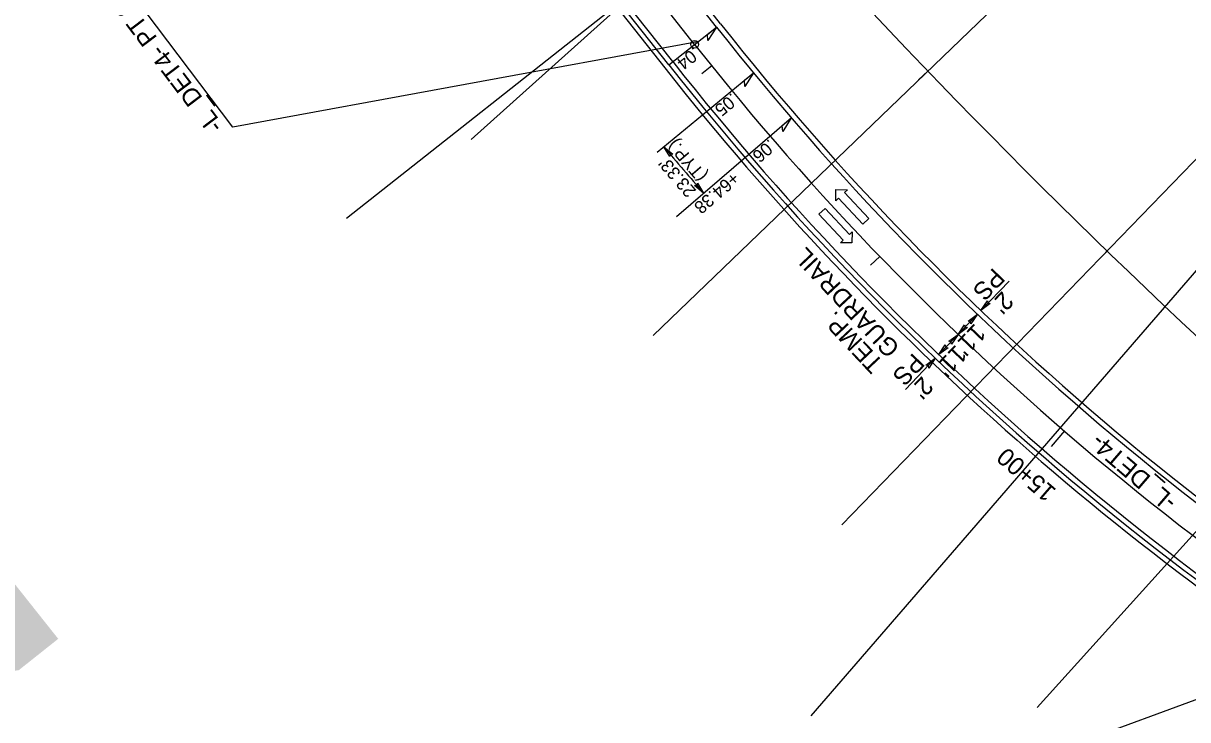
# Model space of a CAD drawing. Extents: x 473658 to 481584, y 489119 to 506230.
# Drawn here: x 476198.9 to 476657.4, y 500561 to 500835 of the extents above; entities that cross this region are included whole.
import ezdxf

# ---------------------------------------------------------------- set-up
doc = ezdxf.new("R2010")
doc.units = 0
for name, color, linetype in [('Exist Horizontal Alignment', 7, 'Continuous'), ('Prop Dimension', 7, 'Continuous'), ('Prop EOT', 7, 'Continuous'), ('Prop Guardrail', 7, 'Continuous'), ('Prop Horizontal Alignment', 7, 'Continuous'), ('Prop Horizontal Alignment Direction Label', 7, 'Continuous'), ('Prop Horizontal Alignment Station Label', 7, 'Continuous'), ('Prop Horizontal Alignment Tick Label', 7, 'Continuous'), ('Prop Horizontal Alignment Tick Large', 7, 'Continuous'), ('Prop Horizontal Alignment Tick Small', 7, 'Continuous'), ('Prop Paved Shoulder', 7, 'Continuous'), ('Prop Shade Medium', 7, 'Continuous'), ('Prop Superelevation  Arrow CELL', 7, 'Continuous'), ('Prop Superelevation Label', 7, 'Continuous'), ('Scratch_Level_6', 7, 'Continuous'), ('Sheet Block Title CELL', 7, 'Continuous'), ('Sheet Plan And Profile CELL', 7, 'Continuous'), ('Sheet Profile Grid Major CELL', 7, 'Continuous')]:
    doc.layers.add(name, color=color, linetype=linetype)

msp = doc.modelspace()

# ---------------------------------------------------------------- linework, layer by layer
at = {"layer": 'Exist Horizontal Alignment'}
for points in [[(476579.63, 500724.73), (476575.96, 500722.01), (476578.51, 500725.83), (476578.69, 500724.86)], [(476570.91, 500717.85), (476574.58, 500720.56), (476572.03, 500716.74), (476571.85, 500717.71)], [(476570.65, 500715.33), (476566.98, 500712.61), (476569.53, 500716.44), (476569.71, 500715.47)], [(476563.31, 500709.9), (476566.98, 500712.61), (476564.43, 500708.79), (476564.25, 500709.76)], [(476563.04, 500707.38), (476559.37, 500704.66), (476561.92, 500708.49), (476562.1, 500707.52)], [(476554.32, 500700.5), (476557.99, 500703.22), (476555.44, 500699.39), (476555.26, 500700.36)]]:
    msp.add_lwpolyline(points, close=True, dxfattribs=at)
at = {"layer": 'Prop Dimension'}
for p, q in [((476575.96, 500722.01), (476587.03, 500733.58)), ((476559.37, 500704.66), (476574.58, 500720.56)), ((476546.24, 500690.93), (476557.99, 500703.22))]:
    msp.add_line(p, q, dxfattribs=at)
at = {"layer": 'Prop EOT'}
for p, q in [((476471.89, 500833.57), (476404.54, 500919.03)), ((476454.61, 500819.95), (476387.26, 500905.41))]:
    msp.add_line(p, q, dxfattribs=at)
for radius, end in [(1089, 241.8577), (1111, 241.40091)]:
    msp.add_arc((477327.21, 501507.62), radius, 218.24077, end, dxfattribs=at)
at = {"layer": 'Prop Guardrail'}
msp.add_line((476384.12, 500902.94), (476451.47, 500817.48), dxfattribs=at)
msp.add_arc((477327.21, 501507.62), 1115, 218.24077, 239.00479, dxfattribs=at)
at = {"layer": 'Prop Horizontal Alignment'}
msp.add_line((476463.25, 500826.76), (476395.9, 500912.22), dxfattribs=at)
for centre, radius, start, end in [((478615.62, 502799.59), 2860, 203.81642, 228.24762), ((477327.21, 501507.62), 1100, 218.24077, 241.8577)]:
    msp.add_arc(centre, radius, start, end, dxfattribs=at)
at = {"layer": 'Prop Horizontal Alignment Station Label'}
for p, q in [((476281.48, 500794.12), (476201.88, 500899.28)), ((476464.43, 500827.69), (476281.48, 500794.12)), ((476772.09, 500609.96), (476453.22, 500492.62))]:
    msp.add_line(p, q, dxfattribs=at)
msp.add_circle((476463.25, 500826.76), 1.5, dxfattribs=at)
at = {"layer": 'Prop Horizontal Alignment Tick Large'}
msp.add_line((476608.81, 500674.62), (476603.58, 500668.56), dxfattribs=at)
at = {"layer": 'Prop Horizontal Alignment Tick Small'}
for p, q in [((476469.99, 500818.3), (476466.09, 500815.17)), ((476555.03, 500816.27), (476551.43, 500812.8)), ((476536.13, 500743.3), (476532.53, 500739.83)), ((476625.62, 500745.44), (476622.15, 500741.85))]:
    msp.add_line(p, q, dxfattribs=at)
at = {"layer": 'Prop Paved Shoulder'}
for p, q in [((476473.46, 500834.81), (476406.11, 500920.27)), ((476453.04, 500818.71), (476385.69, 500904.17))]:
    msp.add_line(p, q, dxfattribs=at)
for radius, end in [(1087, 241.8577), (1113, 241.70868)]:
    msp.add_arc((477327.21, 501507.62), radius, 218.24077, end, dxfattribs=at)
at = {"layer": 'Prop Shade Medium'}
for p, q in [((476518.77, 500765.19), (476518.89, 500769.6)), ((476519.87, 500766.21), (476518.77, 500765.19)), ((476518.89, 500769.6), (476523.37, 500769.48)), ((476529.42, 500755.97), (476519.87, 500766.21)), ((476523.37, 500769.48), (476522.28, 500768.46)), ((476522.28, 500768.46), (476531.83, 500758.23)), ((476512.18, 500759.95), (476514.58, 500762.21)), ((476514.58, 500762.21), (476524.16, 500752)), ((476521.76, 500749.74), (476512.18, 500759.95)), ((476531.83, 500758.23), (476529.42, 500755.97)), ((476524.16, 500752), (476525.26, 500753.03)), ((476525.26, 500753.03), (476525.15, 500748.61)), ((476520.66, 500748.72), (476521.76, 500749.74)), ((476525.15, 500748.61), (476520.66, 500748.72))]:
    msp.add_line(p, q, dxfattribs=at)
at = {"layer": 'Prop Superelevation  Arrow CELL'}
for points in [[(476471.9, 500833.56), (476468.42, 500828.27), (476468.26, 500830.69)], [(476486.39, 500815.57), (476483.02, 500810.22), (476482.82, 500812.63)], [(476501.25, 500797.9), (476498.01, 500792.47), (476497.74, 500794.88)], [(476453.45, 500782.57), (476451.1, 500786.49), (476454.66, 500783.58), (476453.68, 500783.49)], [(476464.42, 500772.18), (476466.76, 500768.26), (476463.21, 500771.17), (476464.19, 500771.26)]]:
    msp.add_lwpolyline(points, close=True, dxfattribs=at)
at = {"layer": 'Prop Superelevation Label'}
for p, q in [((476453.04, 500818.7), (476471.9, 500833.56)), ((476448.49, 500784.38), (476486.39, 500815.57)), ((476456.07, 500759.07), (476501.25, 500797.9))]:
    msp.add_line(p, q, dxfattribs=at)
msp.add_arc((477360.12, 501551.35), 1187.99, 220.07604, 221.23667, dxfattribs=at)
at = {"layer": 'Scratch_Level_6'}
for p, q in [((476326.13, 500758.42), (476561.76, 500944.11)), ((476509.12, 500562.51), (476705.47, 500789.34))]:
    msp.add_line(p, q, dxfattribs=at)
at = {"layer": 'Sheet Plan And Profile CELL'}
for p, q in [((476375.32, 500789.33), (476598.6, 500989.69)), ((476446.96, 500712.24), (476663.1, 500920.29)), ((476521.25, 500637.71), (476729.99, 500853.18)), ((476598.11, 500565.82), (476799.19, 500788.45))]:
    msp.add_line(p, q, dxfattribs=at)

# ---------------------------------------------------------------- texts
at = {"layer": 'Prop Horizontal Alignment Direction Label'}
msp.add_text('-L_DET4-', height=7, rotation=139.2248, dxfattribs=at).set_placement((476653.56, 500647.61))
at = {"layer": 'Prop Horizontal Alignment Station Label'}
msp.add_text('-L_DET4- PT Sta.  17+10.81', height=7, rotation=127.1236, dxfattribs=at).set_placement((476277.94, 500794.9))
at = {"layer": 'Prop Horizontal Alignment Tick Label'}
msp.add_text('15+00', height=7, rotation=139.2248, dxfattribs=at).set_placement((476606, 500651.42))
at = {"layer": 'Prop Superelevation Label'}
for s, rotation, p in [('.04', 218.2326, (476463.02, 500826.05)), ('.05', 219.4565, (476477.85, 500807.85)), ('(TYP.)', 130.6708, (476468.5, 500775.31)), ('.06', 220.6717, (476492.6, 500789.69)), ("23.33'", 130.6708, (476464.13, 500769.21)), ('+64.38', 220.6708, (476478.23, 500776.89))]:
    msp.add_text(s, height=5, rotation=rotation, dxfattribs=at).set_placement(p)
at = {"layer": 'Sheet Block Title CELL'}
msp.add_text('4', height=200, rotation=128.4488, dxfattribs=at).set_placement((476251.95, 500616.18))
at = {"layer": 'Sheet Profile Grid Major CELL'}
for s, rotation, p in [('GUARDRAIL', 133.1753, (476544.43, 500707.57)), ('PS', 226.2809, (476580.91, 500739.16)), ("2'", 226.2809, (476584.43, 500730)), ('TEMP. ', 133.1753, (476537.96, 500701.49)), ("11'", 226.2809, (476573.56, 500717.3)), ("11'", 226.2809, (476566.1, 500708.95)), ('PS', 226.2809, (476549.32, 500705.66)), ("2'", 226.2809, (476552.84, 500696.5))]:
    msp.add_text(s, height=7, rotation=rotation, dxfattribs=at).set_placement(p)

doc.saveas('drawing.dxf')
